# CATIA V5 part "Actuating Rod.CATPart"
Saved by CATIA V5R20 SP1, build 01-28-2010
Part number: Actuating Rod
Bounding box of the stored display mesh (mm): x -17.5 to 17.5, y -11.818 to 195.322, z -21 to 21
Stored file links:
  D:\v5_r20\psrt_files_downloaded\c13-catia-v5r20-prt\c13-catia-v5r20-figr-13-41\Part & Asm files\Actuating Rod.CATPart
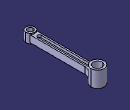
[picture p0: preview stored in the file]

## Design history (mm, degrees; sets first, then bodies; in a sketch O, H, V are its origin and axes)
Body1 (main body)
  Sketch1 on xy-plane, origin (0, 0, 0), H (1, 0, 0), V (0, 1, 0)
    arc A1 centre (0, 0) radius 12 from (-9, 7.9373) to (9, 7.9373) ccw
    arc A2 centre (0, 178) radius 17.5 from (13.5991, 166.9857) to (-13.5991, 166.9857) ccw
    point P1 (0, 178)
    line L1 (9, 154) -> (9, 7.9373)
    point P2 (9, 154)
    point P3 (9, 7.9373)
    arc A3 centre (29.6324, 154) radius 20.6324 from (9, 154) to (13.5991, 166.9857) cw
    point P5 (13.5991, 166.9857)
    point P6 (-13.5991, 166.9857)
    point P7 (-9, 154)
    arc A4 centre (-29.6324, 154) radius 20.6324 from (-9, 154) to (-13.5991, 166.9857) ccw
    point P9 (-9, 7.9373)
    line L2 (-9, 154) -> (-9, 7.9373)
    radius A2 = 17.5
    radius A1 = 12
    distance O P1 = 178
    distance V L1 = 9
    distance P1 P2 V = 24
    coincidence: P1 V
    vertical: L1 V
    tangency: A3 L1, A3 A2
    symmetry: P5 P6 V, P2 P7 V, A3 A4 V, P3 P9 V, L1 L2 V
  Pad1: profile Sketch1, direction (0, 0, 1), length 9, mirrored extent
  Sketch2 on xy-plane, origin (0, 0, 0), H (1, 0, 0), V (0, 1, 0)
    circle A1 centre (0, 0) radius 12
    reference projected arc E1 centre (0, 0) radius 12 from (-9, 7.9373) to (9, 7.9373) ccw from edge of Pad1
    reference projected arc E2 centre (0, 0) radius 12 from (-9, 7.9373) to (9, 7.9373) ccw from edge of Pad1
    reference projected arc E3 centre (0, 0) radius 12 from (-9, 7.9373) to (9, 7.9373) ccw from edge of Pad1
    concentricity: A1 E1, A1 E2
    tangency: A1 E3
  Pad2: profile Sketch2, direction (0, 0, 1), length 12, mirrored extent
  Sketch3 on xy-plane, origin (0, 0, 0), H (1, 0, 0), V (0, 1, 0)
    circle A1 centre (0, 178) radius 17.5
    point P1 (0, 178)
    reference projected arc E1 centre (0, 178) radius 17.5 from (13.5991, 166.9857) to (-13.5991, 166.9857) ccw from edge of Pad1
    reference projected arc E2 centre (0, 178) radius 17.5 from (13.5991, 166.9857) to (-13.5991, 166.9857) ccw from edge of Pad1
    coincidence: P1 V
    concentricity: A1 E1
    tangency: E2 A1
  Pad3: profile Sketch3, direction (0, 0, 1), length 21, mirrored extent
  Sketch4 on xy-plane, origin (0, 0, 0), H (1, 0, 0), V (0, 1, 0)
    circle A1 centre (0, 178) radius 12
    point P1 (0, 178)
    circle A2 centre (0, 0) radius 7.5
    reference projected circle E1 centre (0, 178) radius 17.5 from edge of Pad3
    radius A1 = 12
    radius A2 = 7.5
    coincidence: P1 V
    concentricity: A1 E1
  Pocket1: profile Sketch4, direction (0, 0, -1), length 21, mirrored extent
  Sketch5 on xy-plane, origin (0, 0, 0), H (1, 0, 0), V (0, 1, 0)
    construction line L1 (0, 24) -> (0, 154)
    point P1 (0, 24)
    line L2 (-5, 24) -> (-5, 154)
    line L3 (5, 154) -> (5, 24)
    arc A1 centre (0, 154) radius 5 from (-5, 154) to (5, 154) cw
    arc A2 centre (0, 24) radius 5 from (5, 24) to (-5, 24) cw
    length L1 = 130
    distance H P1 = 24
    radius A1 = 5
    coincidence: P1 V
    vertical: L1 V
    tangency: A1 L2, A2 L2, A1 L3, A2 L3
    parallelism: L1 L2
  Pocket2: profile Sketch5, direction (0, 0, -1), through (limit type 6), opposite side length -2.5
  Mirror1: of Pocket2, Sketch5, about xy-plane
